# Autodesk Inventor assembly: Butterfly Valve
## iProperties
Created: 2002-01
Part Number: Butterfly Valve
Document SubType Name: Assembly
Designer: ***
Control State: 0
Master: False
Checked Out: False
Shininess: 64.0
Length Units: 11269
Angle Units: 11279
Time Units: 11290
Mass Units: 11283
Length Display Precision: 3
Angle Display Precision: 2
Density: 0.0
Volumn: 0.0
Area: 0.0
PropertySet Name: Model Information
Author: ***
